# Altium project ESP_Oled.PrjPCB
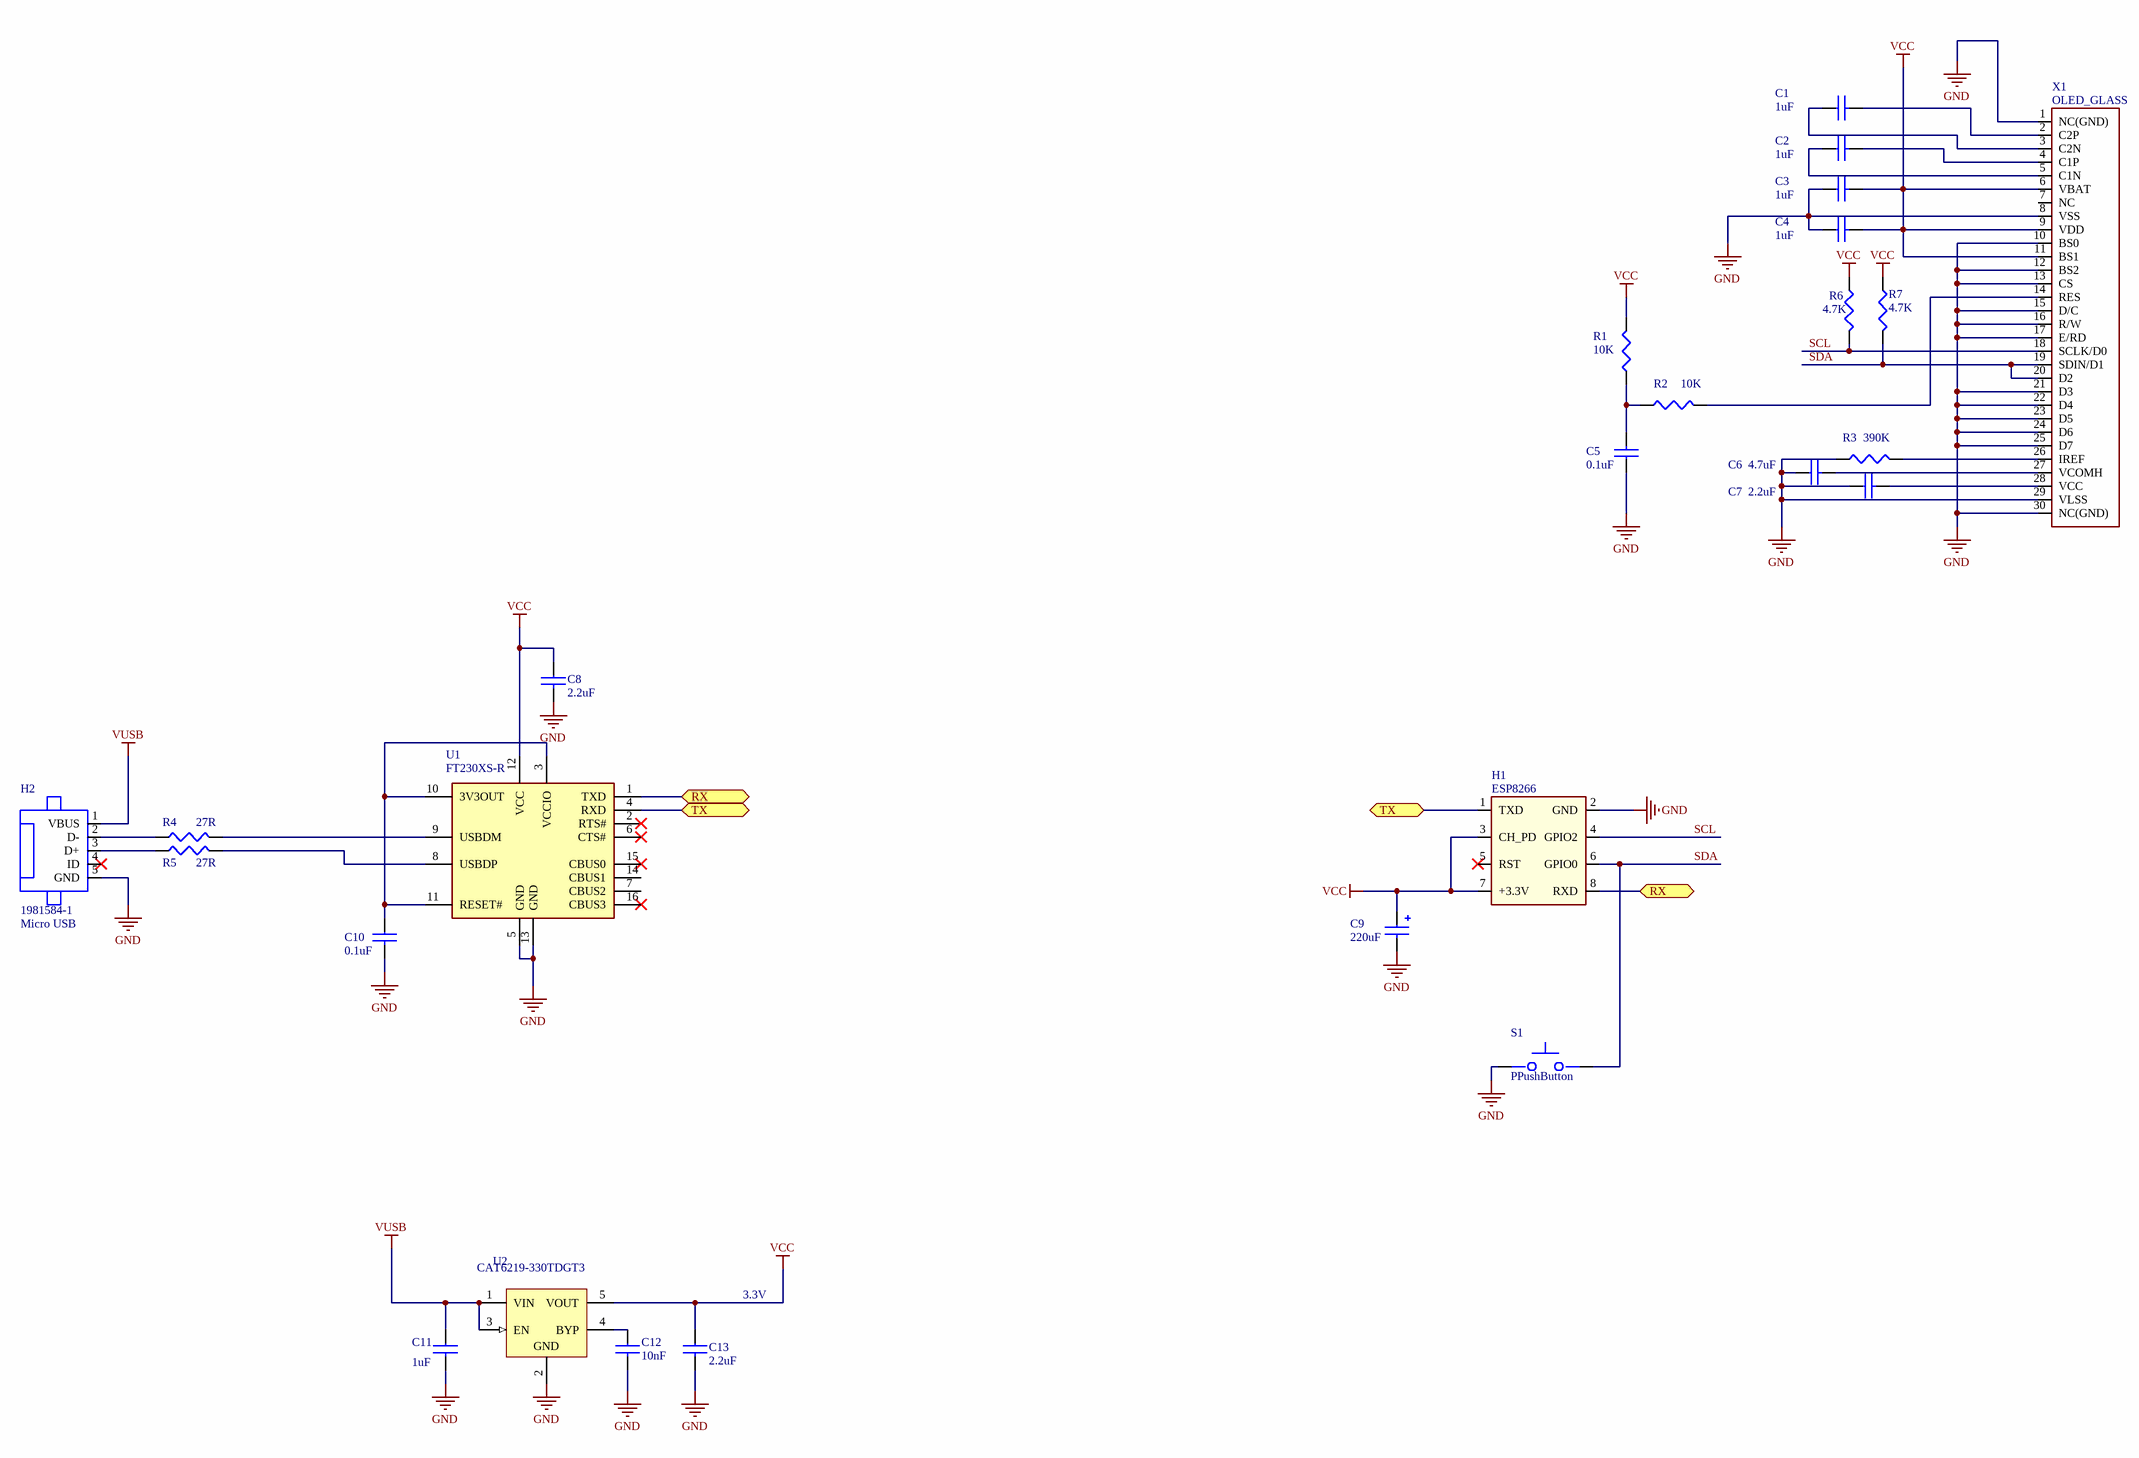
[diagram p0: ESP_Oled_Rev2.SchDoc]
PrjTitle2: -; PrjTitle: ESP Oled Display; PrjStartDate: 2015/06/19; PrjRevision: Rev1; PrjEngineer: MAR; PrjDrawnBy: MAR
1 sheet, 26 parts. Net scope: flat (ports and power ports of the same name join across sheets).
Board file: ESP_Oled_Rev2.PcbDoc

## Sheet ESP_Oled_Rev2.SchDoc
size A2; CompanyName: OMNITECH ELECTRONICS INCORPORATED; Organization: Omnitech Electronics Inc.; Address1: 1-10 Akerley Blvd, Dartmouth, Nova Scotia, Canada B3B 1J4; Address2: (902) 468-5911, FAX (902) 468-5912; Address3: www.omnitechelectronics.ca; SheetTotal: 5; PageSetup: Record=PageOptions¦CenterHorizontal=True¦CenterVertical=True¦PrintScale=0.67¦XCorrection=1.00¦YCorrection=1.00¦PrintKind=1¦BorderSize=5000000¦LeftOffset=0¦BottomOffset=0¦Orientation=2¦PaperLength=1000¦PaperWidth=1000¦Scale=100¦PaperSource=15¦PrintQuality=600¦MediaType=1¦DitherType=10¦PaperKind=11x17¦PrintScaleMode=1

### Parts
C1  1uF  [CHIP_1005L]
C2  1uF  [CHIP_1005L]
C3  1uF  [CHIP_1005L]
C4  1uF  [CHIP_1005L]
C5  0.1uF  [CHIP_1005L]
C6  4.7uF  [CAPC1608X09L]
C7  2.2uF  [CHIP_1005L]
C8  2.2uF  [CHIP_1005L]
C9  220uF  [CAPMP6032X260N_POL]
C10  0.1uF  [CHIP_1005L]
C11  1uF  [CHIP_1005L]
C12  10nF  [CHIP_1005L]
C13  2.2uF  [CHIP_1005L]
H1  (no value)  [ESP8266]
H2  Micro USB  [1981584-1]
R1  10K  [CHIP_1005L]
R2  10K  [CHIP_1005L]
R3  390K  [CHIP_1005L]
R4  27R  [CHIP_1005L]
R5  27R  [CHIP_1005L]
R6  4.7K  [CHIP_1005L]
R7  4.7K  [CHIP_1005L]
S1  PPushButton  [TL1015AF160QG]
U1  (no value)  [SOP65P602X173-16N]
U2  CAT6219-330TDGT3  [ONSC-SOT23-5_L]
X1  OLED_GLASS  [OLED_GLASS 0.96 INCH]

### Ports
RX (bidir), TX (bidir)

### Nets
GND: C3.1 C4.1 C5.1 C6.1 C7.1 C8.2 C9.2 C10.2 C11.2 C12.2 C13.2 H1.2(GND) H2.5(GND) R3.1 S1.1(A) U1.5(GND) U1.13(GND) U2.2(GND) X1.1(NC(GND)) X1.8(VSS) X1.10(BS0) X1.12(BS2) X1.13(CS) X1.15(D/C) X1.16(R/W) X1.17(E/RD) X1.21(D3) X1.22(D4) X1.23(D5) X1.24(D6) X1.25(D7) X1.29(VLSS) X1.30(NC(GND))
VCC: C3.2 C4.2 C8.1 C9.1 C13.1 H1.3(CH_PD) H1.7(+3.3V) R1.2 R6.1 R7.1 U1.12(VCC) U2.5(VOUT) X1.6(VBAT) X1.9(VDD) X1.11(BS1)
VUSB: C11.1 H2.1(VBUS) U2.1(VIN) U2.3(EN)
SCL: H1.4(GPIO2) R6.2 X1.18(SCLK/D0)
SDA: H1.6(GPIO0) R7.2 S1.2(B) X1.19(SDIN/D1) X1.20(D2)
NetC1_1: C1.1 X1.3(C2N)
NetC1_2: C1.2 X1.2(C2P)
NetC2_1: C2.1 X1.5(C1N)
NetC2_2: C2.2 X1.4(C1P)
NetC5_2: C5.2 R1.1 R2.1
NetC6_2: C6.2 X1.27(VCOMH)
NetC7_2: C7.2 X1.28(VCC)
NetC10_1: C10.1 U1.3(VCCIO) U1.10(3V3OUT) U1.11(RESET#)
NetC12_1: C12.1 U2.4(BYP)
NetH1_1: H1.1(TXD) U1.4(RXD) ; port TX
NetH1_8: H1.8(RXD) U1.1(TXD) ; port RX
NetH2_2: H2.2(D-) R4.1
NetH2_3: H2.3(D+) R5.1
NetR2_2: R2.2 X1.14(RES)
NetR3_2: R3.2 X1.26(IREF)
NetR4_2: R4.2 U1.9(USBDM)
NetR5_2: R5.2 U1.8(USBDP)

Not connected (* = marked no-connect by the designer): H1 5(RST)*; H2 4(ID)*; U1 2(RTS#)* 6(CTS#)* 7(CBUS2) 14(CBUS1) 15(CBUS0)* 16(CBUS3)*; X1 7(NC)

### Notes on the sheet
- 3.3V

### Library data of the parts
C1-C4 C11 = CAP_0603: CAP CER 1UF 16V 10% X5R 0402; PartNumber: C1005X5R1C105K050BC; Manufacturer: TDK; Vendor: Digi-Key
C5 C10 = CAP_0603: CAP CER 0.1UF 25V 10% X7R 0402; PartNumber: C1005X7R1E104K050BB; Manufacturer: TDK; Vendor: Digi-Key
C6 = CAP_0603: CAP CER 4.7UF 16V 10% X5R 0603; PartNumber: C1608X5R1C475K080AC; Manufacturer: TDK; Vendor: Digi-Key
C7 = CAP_0603: CAP CER 2.2UF 16V 20% X5R 0402; PartNumber: C1005X5R1C225M050BC; Manufacturer: TDK; Vendor: Digi-Key
C8 C13 = CAP_0805: CAP CER 2.2UF 16V 20% X5R 0402; Manufacturer: TDK; PartNumber: C1005X5R1C225M050BC; Vendor: Digi-Key
C9 = CAP_TANT_6032: CAP TANT 220UF 6.3V 10% 2312; PartNumber: T495C227K006ATE225; Manufacturer: Kemet; Vendor: Digi-Key
C12 = CAP_0603: CAP CER 1000PF 50V 5% C0G 0402; PartNumber: C1005C0G1H102J050BA; Manufacturer: TDK; Vendor: Digi-Key
H1 = ESP8266
H2 = 1981584-1: CONN RCPT MICRO USB TYPE AB; Manufacturer: TE Connectivity; Vendor: Digi-Key
R1 R2 = RES_0603: RES SMD 10K OHM 1% 1/10W 0402; Manufacturer: Panasonic; PartNumber: ERJ-2RKF1002X; Vendor: Digi-Key
R3 = RES_0603: RES SMD 390K OHM 1% 1/10W 0402; Manufacturer: Panasonic; PartNumber: ERJ-2RKF3903X; Vendor: Digi-key
R4 R5 = RES_0603: RES SMD 27 OHM 1% 1/10W 0402; Manufacturer: Panasonic; PartNumber: ERJ-2RKF27R0X; Vendor: Digi-Key
R6 = RES_0402: RES SMD 4.7K OHM 5% 1/10W 0402; PartNumber: ERJ-2GEJ472X; Manufacturer: Panasonic; Vendor: Digi-key
R7 = RES_0402: RES SMD 4.7K OHM 5% 1/10W 0402; PartNumber: ERJ-2GEJ472X; Manufacturer: Panasonic; Vendor: Digi-Key
S1 = DX_MINI_TACT_SWITCH: DX_SWITCH TACTILE; PartNumber: 122514; Value: Mini PushButton; Vendor: DX.com
U1 = FT230XS-R: IC USB SERIAL BASIC UART 16SSOP; Manufacturer: FTDI; Vendor: Digi-key
U2 = CMP-0273-00001-2: IC REG LDO 3.3V 0.5A TSOT23-5; Manufacturer: ON Semiconductor; Vendor: Digi-Key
